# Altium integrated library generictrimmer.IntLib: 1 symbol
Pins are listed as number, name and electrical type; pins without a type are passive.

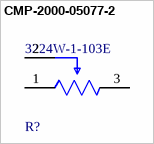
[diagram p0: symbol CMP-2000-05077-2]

## CMP-2000-05077-2
designator R?, comment 3224W-1-103E
TRIMMER 10K OHM 0.25W J LEAD TOP; Manufacturer: Bourns; Tolerance: 10%; Resistance: 10kΩ; Temperature Coefficient: 100ppm/°C; Value: 10kΩ; Standoff Height: 0.2mm; Voltage Rating: 300V; Power Rating: 250mW
footprint FP-3224W-MFG
pins: 1 CCW, 2 WIPER, 3 CW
